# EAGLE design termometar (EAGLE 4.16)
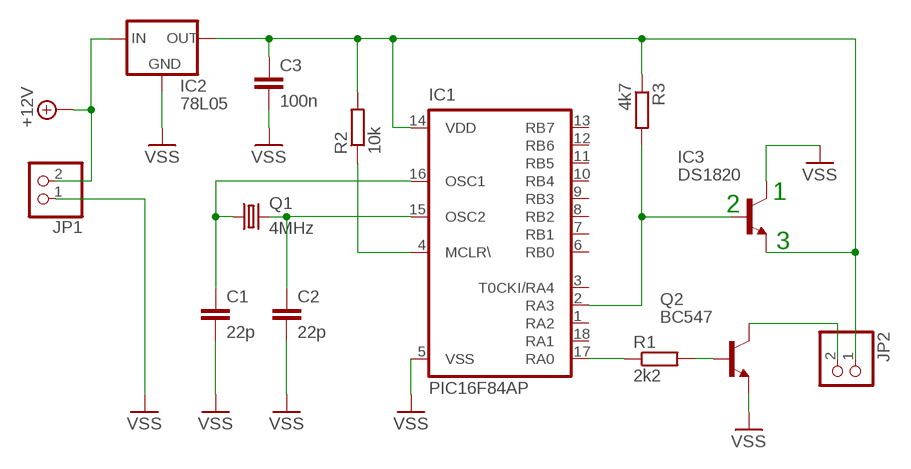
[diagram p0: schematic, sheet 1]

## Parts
C1  22p  C-EU050-024X044  [C050-024X044]
C2  22p  C-EU050-024X044  [C050-024X044]
C3  100n  C-EU050-024X044  [C050-024X044]
IC1  PIC16F84AP  [DIL18]
IC2  78L05  78LXX  [78LXX]
IC3  DS1820  BC338  [TO92-EBC]
JP1  PINHD-1X2_2.54  [1X02]
JP2  PINHD-1X2_2.54  [1X02]
Q1  4MHz  CRYSTALHC49S  [HC49/S]
Q2  BC547  [TO92]
R1  2k2  R-EU_0204/7  [0204/7]
R2  10k  R-EU_0204/7  [0204/7]
R3  4k7  R-EU_0204/7  [0204/7]

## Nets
+12V: IC2.IN JP1.2
N$1: C1.1 IC1.16(OSC1) Q1.1
N$2: C2.1 IC1.15(OSC2) Q1.2
N$3: IC1.17(RA0) R1.1
N$4: Q2.2(B) R1.2
N$5: JP2.2 Q2.3(C)
N$6: IC1.2(RA3) IC3.B R3.2
N$7: C3.1 IC1.14(VDD) IC2.OUT IC3.E JP2.1 R2.2 R3.1
N$8: IC1.4(MCLR\) R2.1
VSS: C1.2 C2.2 C3.2 IC1.5(VSS) IC2.GND IC3.C JP1.1 Q2.1(E)
Unconnected: IC1.1(RA2) IC1.3(T0CKI/RA4) IC1.6(RB0) IC1.7(RB1) IC1.8(RB2) IC1.9(RB3) IC1.10(RB4) IC1.11(RB5) IC1.12(RB6) IC1.13(RB7) IC1.18(RA1)

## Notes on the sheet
- 1
- 2
- 3

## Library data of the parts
C1-C3 = rcl:C-EU: CAPACITOR, European symbol
IC1 = microchip:PIC16F8*: MICROCONTROLLER 8-Bit PIC16F8X Family - CMOS Flash/EEPROM Pin Compatible : PIC16F83, PIC16CR83, PIC16F84A, PIC16CR84 see also PIC16C*
IC2 = v-reg:78LXX: VOLTAGE REGULATOR
IC3 = transistor-npn:BC338*: NPN Transistor
JP1 JP2 = pinhead:PINHD-1X2: PIN HEADER
Q1 = crystal:CRYSTAL: CRYSTAL
Q2 = transistor-npn:BC547*: NPN Transistor
R1-R3 = rcl:R-EU_: RESISTOR, European symbol

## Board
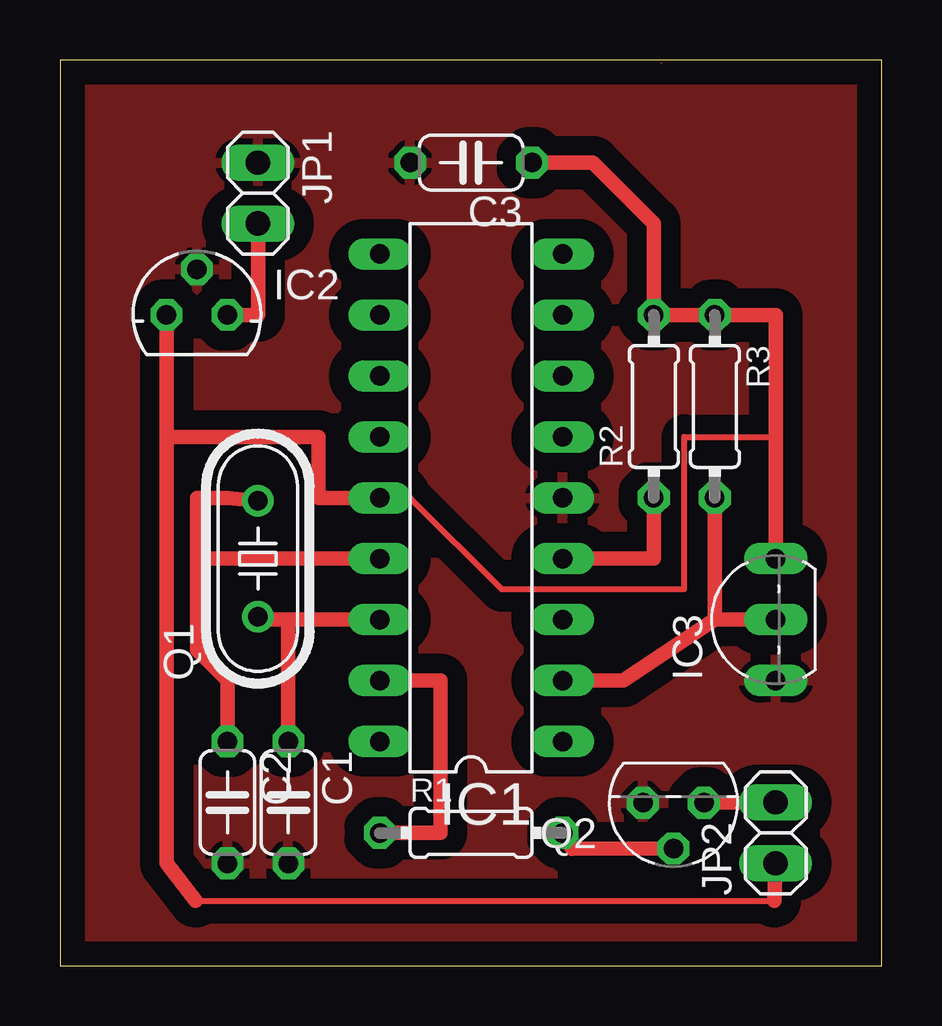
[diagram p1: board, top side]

Size 34.27 x 37.77 mm. Coordinates in mm from the lower left corner, seen from the top.
Outline: 0,0 34.27,0 34.27,37.77 0,37.77 0,0
Copper layers (1*16): Top 0.035mm / dielectric 1.5mm / Bottom 0.035mm
Design rules "default": minimum track width 10mil, minimum drill 24mil, track to track 8mil, track to pad 8mil, pad to pad 8mil, via to via 8mil, smd to smd 8mil, copper to edge 40mil, drill to drill 8mil, minimum pad ring 10mil, minimum via ring 8mil, stop-mask expansion 4mil, vias tented up to drill 0mil, thermal gap 10mil

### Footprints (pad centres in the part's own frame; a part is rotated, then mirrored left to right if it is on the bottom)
C050-024X044 = drill 0.813 octagon: 1 -2.54,0; 2 2.54,0
DIL18 = drill 0.813 long: 1 -10.16,-3.81; 2 -7.62,-3.81; 3 -5.08,-3.81; 4 -2.54,-3.81; 5 0,-3.81; 6 2.54,-3.81; 7 5.08,-3.81; 8 7.62,-3.81; 9 10.16,-3.81; 10 10.16,3.81; 11 7.62,3.81; 12 5.08,3.81; 13 2.54,3.81; 14 0,3.81; 15 -2.54,3.81; 16 -5.08,3.81; 17 -7.62,3.81; 18 -10.16,3.81
78LXX = drill 0.813 octagon: GND 0,1.905; IN 1.27,0; OUT -1.27,0
TO92-EBC = drill 0.813 long: B 0,-1.27; C -2.54,-1.27; E 2.54,-1.27
1X02 = drill 1.016 long: 1 -1.27,0; 2 1.27,0
HC49/S = drill 0.813 round: 1 -2.413,0; 2 2.413,0
TO92 = drill 0.813 octagon: 1 1.27,0; 2 0,1.905; 3 -1.27,0
0204/7 = drill 0.813 octagon: 1 -3.81,0; 2 3.81,0

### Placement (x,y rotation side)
C1  9.52,6.82 270 top
C2  6.98,6.82 270 top
C3  17.14,33.49 180 top
IC1  17.14,19.52 90 top
IC2  5.71,27.14 0 top
IC3  28.57,14.44 90 top
JP1  8.25,32.22 270 top
JP2  29.84,5.55 90 top
Q1  8.25,16.98 90 top
Q2  25.57,6.8 180 top
R1  17.14,5.55 0 top
R2  24.76,23.33 90 top
R3  27.3,23.33 270 top

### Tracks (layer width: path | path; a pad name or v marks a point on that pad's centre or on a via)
+12V
  Top 0.61: IC2.IN 8.25,27.14 JP1.2
N$1
  Top 0.254: 8.25,14.44 Q1.1
  Top 0.61: C1.1 9.52,14.44 | 9.52,14.44 8.25,14.44 | 9.52,14.44 IC1.16
N$2
  Top 0.61: C2.1 6.98,11.9 5.71,13.17 5.71,16.98 | 5.71,16.98 5.71,19.52 6.98,19.52 Q1.2 | 5.71,16.98 IC1.15
N$3
  Top 0.61: R1.1 15.87,5.55 15.87,11.9 IC1.17
N$4
  Top 0.61: R1.2 21.34,4.88 Q2.2
N$5
  Top 0.61: Q2.3 JP2.2
N$6
  Top 0.61: 27.3,14.44 23.49,11.9 IC1.2 | 27.3,14.44 IC3.B | 27.3,14.44 R3.2
N$7
  Top 0.254: R3.1 R2.2 | 5.65,2.71 29.78,2.71 | 29.84,22.06 26.03,22.06 26.03,15.71 18.41,15.71 14.6,19.52 IC1.14
  Top 0.61: C3.1 22.22,33.49 24.76,30.95 R2.2 R3.1 29.84,27.14 29.84,22.06 IC3.E | 4.44,22.06 IC2.OUT | IC1.14 10.79,19.52 10.79,22.06 4.44,22.06 | 5.65,2.71 4.44,4.28 4.44,22.06 | 29.78,2.71 JP2.1
N$8
  Top 0.61: R2.1 24.76,16.98 IC1.4
N$10
  Top 0: 25.06,37.64 25.1,37.64
VSS
  pour Top (isolate 0.813): -0.64,37.3 34.92,37.3 34.92,0.47 -0.64,0.47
